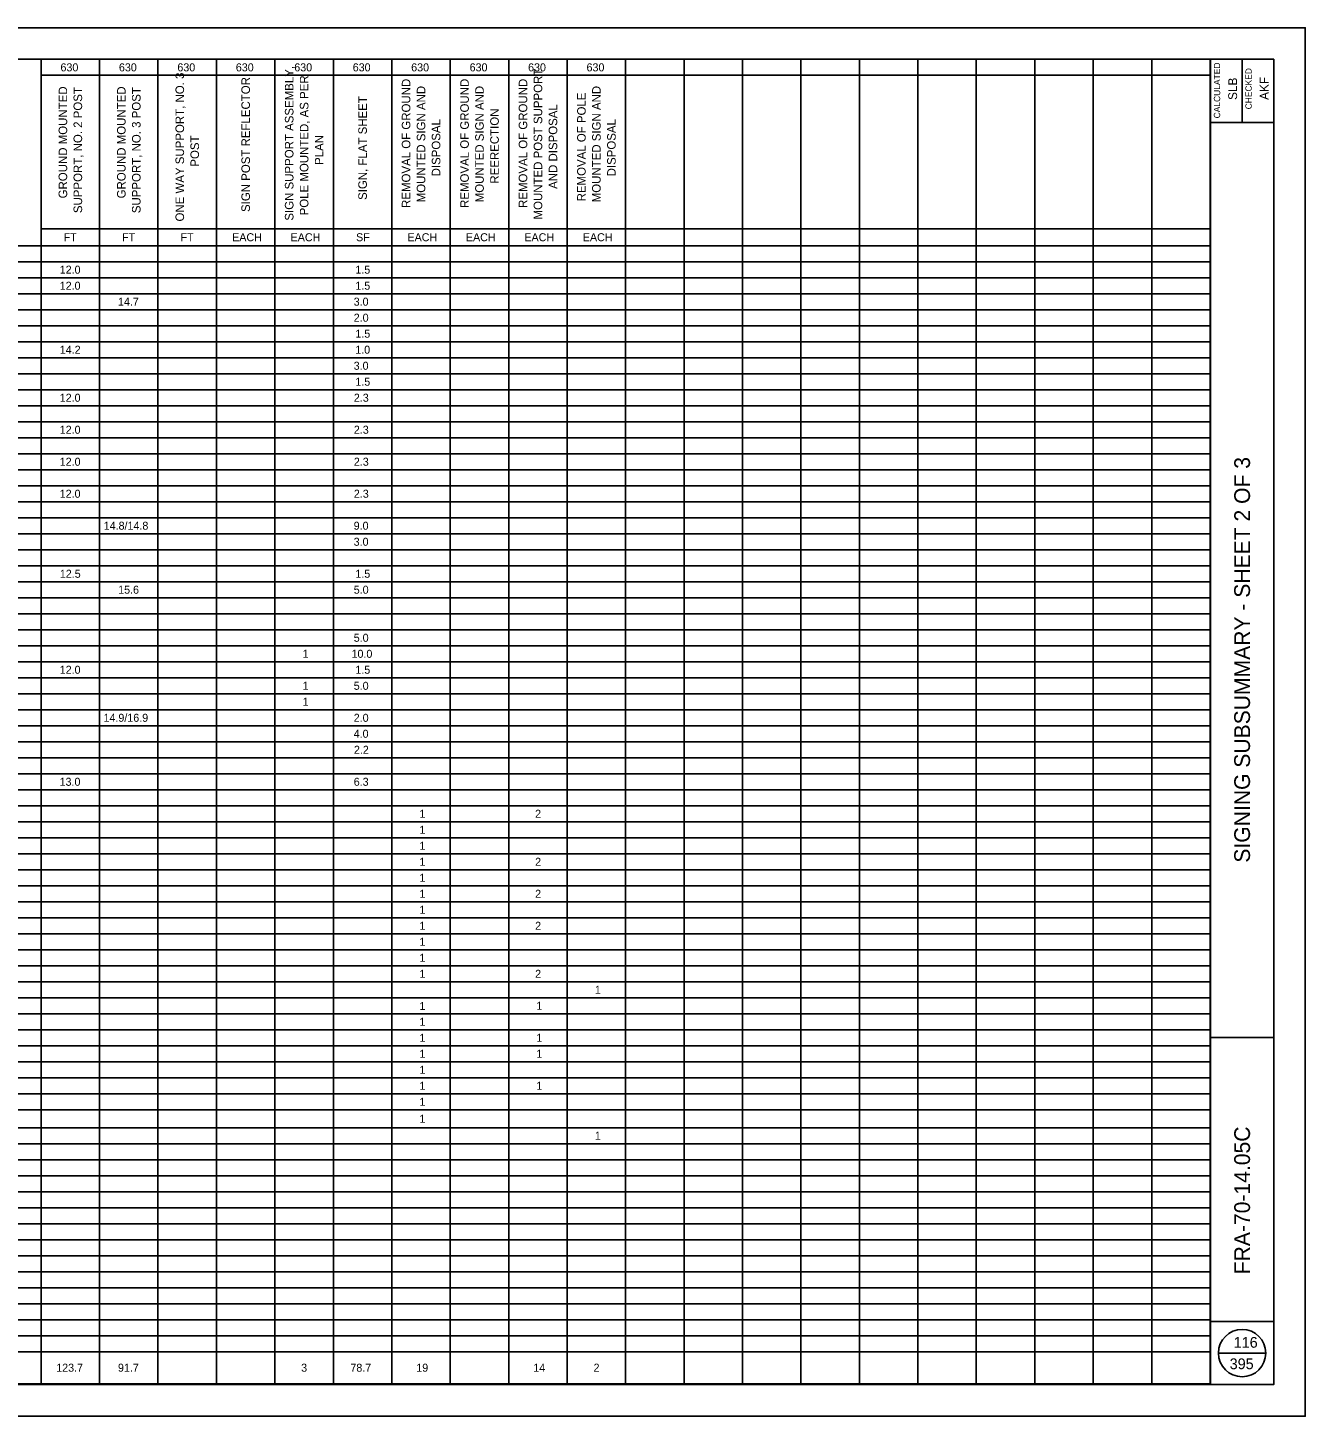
# Model space of a CAD drawing. Extents: x 1822379 to 1824724, y 710341 to 711455.
# Drawn here: x 1822392.87 to 1822413.11, y 711198.87 to 711220.87 of the extents above; entities that cross this region are included whole.
import ezdxf

# ---------------------------------------------------------------- set-up
doc = ezdxf.new("R2010")
doc.units = 0
for name, color, linetype in [('SH_Border', 7, 'Continuous'), ('SH_Cut_Line', 7, 'Continuous'), ('SH_Data', 7, 'Continuous'), ('SH_Text', 7, 'Continuous'), ('TX_P_20', 7, 'Continuous')]:
    doc.layers.add(name, color=color, linetype=linetype)

msp = doc.modelspace()

# ---------------------------------------------------------------- linework, layer by layer
at = {"layer": 'SH_Border'}
for p, q in [((1822411.613, 711199.366), (1822411.613, 711220.366)), ((1822412.113, 711220.366), (1822412.113, 711219.366)), ((1822411.613, 711219.366), (1822412.613, 711219.366)), ((1822411.613, 711204.866), (1822412.613, 711204.866)), ((1822411.613, 711200.366), (1822412.613, 711200.366))]:
    msp.add_line(p, q, dxfattribs=at)
msp.add_lwpolyline([(1822381.113, 711220.366), (1822412.613, 711220.366), (1822412.613, 711199.366), (1822381.113, 711199.366)], close=True, dxfattribs=at)
at = {"layer": 'SH_Cut_Line'}
msp.add_lwpolyline([(1822379.113, 711198.866), (1822413.113, 711198.866), (1822413.113, 711220.866), (1822379.113, 711220.866)], close=True, dxfattribs=at)
at = {"layer": 'SH_Data'}
for p, q in [((1822381.113, 711220.366), (1822411.606, 711220.366)), ((1822393.086, 711220.366), (1822393.086, 711199.38)), ((1822394.012, 711220.366), (1822394.012, 711199.38)), ((1822394.938, 711220.366), (1822394.938, 711199.38)), ((1822395.864, 711220.366), (1822395.864, 711199.38)), ((1822396.79, 711220.366), (1822396.79, 711199.38)), ((1822397.716, 711220.366), (1822397.716, 711199.38)), ((1822398.642, 711220.366), (1822398.642, 711199.38)), ((1822399.568, 711220.366), (1822399.568, 711199.38)), ((1822400.494, 711220.366), (1822400.494, 711199.38)), ((1822401.42, 711220.366), (1822401.42, 711199.38)), ((1822402.346, 711220.366), (1822402.346, 711199.38)), ((1822403.272, 711220.366), (1822403.272, 711199.38)), ((1822404.198, 711220.366), (1822404.198, 711199.38)), ((1822405.124, 711220.366), (1822405.124, 711199.38)), ((1822406.05, 711220.366), (1822406.05, 711199.38)), ((1822406.976, 711220.366), (1822406.976, 711199.38)), ((1822407.902, 711220.366), (1822407.902, 711199.38)), ((1822408.828, 711220.366), (1822408.828, 711199.38)), ((1822409.754, 711220.366), (1822409.754, 711199.38)), ((1822410.68, 711220.366), (1822410.68, 711199.38)), ((1822411.606, 711220.366), (1822411.606, 711199.38)), ((1822393.086, 711220.112), (1822411.606, 711220.112)), ((1822393.086, 711217.681), (1822411.606, 711217.681)), ((1822381.113, 711217.412), (1822411.606, 711217.412)), ((1822381.113, 711217.159), (1822411.606, 711217.159)), ((1822381.113, 711216.905), (1822411.606, 711216.905)), ((1822381.113, 711216.652), (1822411.606, 711216.652)), ((1822381.113, 711216.398), (1822411.606, 711216.398)), ((1822381.113, 711216.145), (1822411.606, 711216.145)), ((1822381.113, 711215.891), (1822411.606, 711215.891)), ((1822381.113, 711215.638), (1822411.606, 711215.638)), ((1822381.113, 711215.384), (1822411.606, 711215.384)), ((1822381.113, 711215.13), (1822411.606, 711215.13)), ((1822381.113, 711214.877), (1822411.606, 711214.877)), ((1822381.113, 711214.623), (1822411.606, 711214.623)), ((1822381.113, 711214.37), (1822411.606, 711214.37)), ((1822381.113, 711214.116), (1822411.606, 711214.116)), ((1822381.113, 711213.863), (1822411.606, 711213.863)), ((1822381.113, 711213.609), (1822411.606, 711213.609)), ((1822381.113, 711213.356), (1822411.606, 711213.356)), ((1822381.113, 711213.102), (1822411.606, 711213.102)), ((1822381.113, 711212.849), (1822411.606, 711212.849)), ((1822381.113, 711212.595), (1822411.606, 711212.595)), ((1822381.113, 711212.341), (1822411.606, 711212.341)), ((1822381.113, 711212.088), (1822411.606, 711212.088)), ((1822381.113, 711211.834), (1822411.606, 711211.834)), ((1822381.113, 711211.581), (1822411.606, 711211.581)), ((1822381.113, 711211.327), (1822411.606, 711211.327)), ((1822381.113, 711211.074), (1822411.606, 711211.074)), ((1822381.113, 711210.82), (1822411.606, 711210.82)), ((1822381.113, 711210.567), (1822411.606, 711210.567)), ((1822381.113, 711210.313), (1822411.606, 711210.313)), ((1822381.113, 711210.059), (1822411.606, 711210.059)), ((1822381.113, 711209.806), (1822411.606, 711209.806)), ((1822381.113, 711209.552), (1822411.606, 711209.552)), ((1822381.113, 711209.299), (1822411.606, 711209.299)), ((1822381.113, 711209.045), (1822411.606, 711209.045)), ((1822381.113, 711208.792), (1822411.606, 711208.792)), ((1822381.113, 711208.538), (1822411.606, 711208.538)), ((1822381.113, 711208.285), (1822411.606, 711208.285)), ((1822381.113, 711208.031), (1822411.606, 711208.031)), ((1822381.113, 711207.777), (1822411.606, 711207.777)), ((1822381.113, 711207.524), (1822411.606, 711207.524)), ((1822381.113, 711207.27), (1822411.606, 711207.27)), ((1822381.113, 711207.017), (1822411.606, 711207.017)), ((1822381.113, 711206.763), (1822411.606, 711206.763)), ((1822381.113, 711206.51), (1822411.606, 711206.51)), ((1822381.113, 711206.256), (1822411.606, 711206.256)), ((1822381.113, 711206.003), (1822411.606, 711206.003)), ((1822381.113, 711205.749), (1822411.606, 711205.749)), ((1822381.113, 711205.496), (1822411.606, 711205.496)), ((1822381.113, 711205.242), (1822411.606, 711205.242)), ((1822381.113, 711204.988), (1822411.606, 711204.988)), ((1822381.113, 711204.735), (1822411.606, 711204.735)), ((1822381.113, 711204.481), (1822411.606, 711204.481)), ((1822381.113, 711204.228), (1822411.606, 711204.228)), ((1822381.113, 711203.974), (1822411.606, 711203.974)), ((1822381.113, 711203.721), (1822411.606, 711203.721)), ((1822381.113, 711203.437), (1822411.606, 711203.437)), ((1822381.113, 711203.184), (1822411.606, 711203.184)), ((1822381.113, 711202.93), (1822411.606, 711202.93)), ((1822381.113, 711202.677), (1822411.606, 711202.677)), ((1822381.113, 711202.423), (1822411.606, 711202.423)), ((1822381.113, 711202.17), (1822411.606, 711202.17)), ((1822381.113, 711201.916), (1822411.606, 711201.916)), ((1822381.113, 711201.662), (1822411.606, 711201.662)), ((1822381.113, 711201.409), (1822411.606, 711201.409)), ((1822381.113, 711201.155), (1822411.606, 711201.155)), ((1822381.113, 711200.902), (1822411.606, 711200.902)), ((1822381.113, 711200.648), (1822411.606, 711200.648)), ((1822381.113, 711200.395), (1822411.606, 711200.395)), ((1822381.113, 711200.141), (1822411.606, 711200.141)), ((1822381.113, 711199.888), (1822411.606, 711199.888)), ((1822411.738, 711199.866), (1822412.488, 711199.866)), ((1822381.113, 711199.38), (1822411.606, 711199.38))]:
    msp.add_line(p, q, dxfattribs=at)
msp.add_circle((1822412.113, 711199.866), 0.375, dxfattribs=at)

# ---------------------------------------------------------------- texts
for s, height, p in [('CALCULATED', 0.1, (1822411.765, 711219.43)), ('CHECKED', 0.1, (1822412.265, 711219.573)), ('SLB', 0.14, (1822412.033, 711219.722)), ('AKF', 0.14, (1822412.533, 711219.723)), ('SIGNING SUBSUMMARY - SHEET 2 OF 3', 0.25, (1822412.238, 711207.637)), ('FRA-70-14.05C', 0.25, (1822412.238, 711201.115))]:
    msp.add_text(s, height=height, rotation=90, dxfattribs=at).set_placement(p)
at = {"layer": 'SH_Text'}
for s, height, p in [('630', 0.1268, (1822393.393, 711220.175)), ('630', 0.1268, (1822394.319, 711220.175)), ('630', 0.1268, (1822395.245, 711220.175)), ('630', 0.1268, (1822396.171, 711220.175)), ('630', 0.1268, (1822397.097, 711220.175)), ('630', 0.1268, (1822398.023, 711220.175)), ('630', 0.1268, (1822398.949, 711220.175)), ('630', 0.1268, (1822399.875, 711220.175)), ('630', 0.1268, (1822400.801, 711220.175)), ('630', 0.1268, (1822401.727, 711220.175)), ('FT', 0.1268, (1822393.443, 711217.483)), ('FT', 0.1268, (1822394.369, 711217.483)), ('FT', 0.1268, (1822395.295, 711217.483)), ('EACH', 0.1268, (1822396.113, 711217.483)), ('EACH', 0.1268, (1822397.039, 711217.483)), ('SF', 0.1268, (1822398.076, 711217.483)), ('EACH', 0.1268, (1822398.89, 711217.483)), ('EACH', 0.1268, (1822399.816, 711217.483)), ('EACH', 0.1268, (1822400.742, 711217.483)), ('EACH', 0.1268, (1822401.668, 711217.483)), ('12.0', 0.1268, (1822393.381, 711216.969)), ('1.5', 0.1268, (1822398.065, 711216.969)), ('12.0', 0.1268, (1822393.381, 711216.715)), ('1.5', 0.1268, (1822398.065, 711216.715)), ('14.7', 0.1268, (1822394.304, 711216.462)), ('3.0', 0.1268, (1822398.038, 711216.462)), ('2.0', 0.1268, (1822398.039, 711216.208)), ('1.5', 0.1268, (1822398.065, 711215.955)), ('14.2', 0.1268, (1822393.382, 711215.701)), ('1.0', 0.1268, (1822398.063, 711215.701)), ('3.0', 0.1268, (1822398.038, 711215.447)), ('1.5', 0.1268, (1822398.065, 711215.194)), ('12.0', 0.1268, (1822393.381, 711214.94)), ('2.3', 0.1268, (1822398.041, 711214.94)), ('12.0', 0.1268, (1822393.381, 711214.433)), ('2.3', 0.1268, (1822398.041, 711214.433)), ('12.0', 0.1268, (1822393.381, 711213.926)), ('2.3', 0.1268, (1822398.041, 711213.926)), ('12.0', 0.1268, (1822393.381, 711213.419)), ('2.3', 0.1268, (1822398.041, 711213.419)), ('14.8/14.8', 0.1268, (1822394.078, 711212.912)), ('9.0', 0.1268, (1822398.038, 711212.912)), ('3.0', 0.1268, (1822398.038, 711212.658)), ('12.5', 0.1268, (1822393.383, 711212.151)), ('1.5', 0.1268, (1822398.065, 711212.151)), ('15.6', 0.1268, (1822394.307, 711211.898)), ('5.0', 0.1268, (1822398.039, 711211.898)), ('5.0', 0.1268, (1822398.039, 711211.137)), ('1', 0.127, (1822397.228, 711210.883)), ('10.0', 0.1268, (1822398.004, 711210.883)), ('12.0', 0.1268, (1822393.381, 711210.63)), ('1.5', 0.1268, (1822398.065, 711210.63)), ('1', 0.127, (1822397.228, 711210.376)), ('5.0', 0.1268, (1822398.039, 711210.376)), ('1', 0.127, (1822397.228, 711210.123)), ('14.9/16.9', 0.1268, (1822394.075, 711209.869)), ('2.0', 0.1268, (1822398.039, 711209.869)), ('4.0', 0.1268, (1822398.038, 711209.616)), ('2.2', 0.1268, (1822398.042, 711209.362)), ('13.0', 0.1268, (1822393.379, 711208.855)), ('6.3', 0.1268, (1822398.039, 711208.855)), ('1', 0.127, (1822399.08, 711208.348)), ('2', 0.127, (1822400.912, 711208.348)), ('1', 0.127, (1822399.08, 711208.094)), ('1', 0.127, (1822399.08, 711207.841)), ('1', 0.127, (1822399.08, 711207.587)), ('2', 0.127, (1822400.912, 711207.587)), ('1', 0.127, (1822399.08, 711207.334)), ('1', 0.127, (1822399.08, 711207.08)), ('2', 0.127, (1822400.912, 711207.08)), ('1', 0.127, (1822399.08, 711206.827)), ('1', 0.127, (1822399.08, 711206.573)), ('2', 0.127, (1822400.912, 711206.573)), ('1', 0.127, (1822399.08, 711206.32)), ('1', 0.127, (1822399.08, 711206.066)), ('1', 0.127, (1822399.08, 711205.812)), ('2', 0.127, (1822400.912, 711205.812)), ('1', 0.127, (1822401.858, 711205.559)), ('1', 0.127, (1822399.08, 711205.302)), ('1', 0.127, (1822400.932, 711205.305)), ('1', 0.127, (1822399.08, 711205.052)), ('1', 0.127, (1822399.08, 711204.798)), ('1', 0.127, (1822400.932, 711204.798)), ('1', 0.127, (1822399.08, 711204.545)), ('1', 0.127, (1822400.932, 711204.545)), ('1', 0.127, (1822399.08, 711204.291)), ('1', 0.127, (1822399.08, 711204.038)), ('1', 0.127, (1822400.932, 711204.038)), ('1', 0.127, (1822399.08, 711203.784)), ('1', 0.127, (1822399.08, 711203.516)), ('1', 0.127, (1822401.858, 711203.247)), ('123.7', 0.1268, (1822393.326, 711199.571)), ('91.7', 0.1268, (1822394.304, 711199.571)), ('3', 0.127, (1822397.206, 711199.571)), ('78.7', 0.1268, (1822397.986, 711199.571)), ('19', 0.1268, (1822399.03, 711199.571)), ('14', 0.1268, (1822400.883, 711199.571)), ('2', 0.127, (1822401.838, 711199.571))]:
    msp.add_text(s, height=height, dxfattribs=at).set_placement(p)
for s, p in [('SIGN SUPPORT ASSEMBLY,', (1822397.084, 711217.81)), ('MOUNTED POST SUPPORT', (1822401.025, 711217.828)), ('ONE WAY SUPPORT, NO. 3', (1822395.351, 711217.796)), ('SIGN POST REFLECTOR', (1822396.395, 711217.947)), ('POLE MOUNTED, AS PER', (1822397.321, 711217.893)), ('REMOVAL OF GROUND', (1822398.936, 711218.011)), ('REMOVAL OF GROUND', (1822399.862, 711218.011)), ('REMOVAL OF GROUND', (1822400.788, 711218.011)), ('GROUND MOUNTED', (1822393.499, 711218.162)), ('SUPPORT, NO. 2 POST', (1822393.736, 711217.929)), ('GROUND MOUNTED', (1822394.425, 711218.162)), ('SUPPORT, NO. 3 POST', (1822394.662, 711217.928)), ('SIGN, FLAT SHEET', (1822398.247, 711218.138)), ('MOUNTED SIGN AND', (1822399.173, 711218.1)), ('MOUNTED SIGN AND', (1822400.099, 711218.1)), ('REMOVAL OF POLE', (1822401.714, 711218.115)), ('MOUNTED SIGN AND', (1822401.951, 711218.1)), ('REERECTION', (1822400.337, 711218.396)), ('AND DISPOSAL', (1822401.263, 711218.313)), ('DISPOSAL', (1822399.411, 711218.511)), ('DISPOSAL', (1822402.189, 711218.511)), ('POST', (1822395.588, 711218.665)), ('PLAN', (1822397.559, 711218.692))]:
    msp.add_text(s, height=0.1357, rotation=90, dxfattribs=at).set_placement(p)
at = {"layer": 'TX_P_20'}
for s, p in [('116', (1822411.98, 711199.951)), ('395', (1822411.916, 711199.611))]:
    msp.add_text(s, height=0.17, dxfattribs=at).set_placement(p)

doc.saveas('drawing.dxf')
